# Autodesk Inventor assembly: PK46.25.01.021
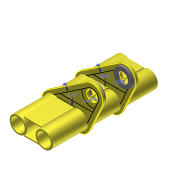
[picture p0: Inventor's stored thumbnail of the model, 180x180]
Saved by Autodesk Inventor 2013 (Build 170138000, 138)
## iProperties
Created: 2005-04
Part Number: PK46.25.01.021
Document SubType Name: Assembly
Designer: salex
Manufacturer: Standard
Standards Organization: Custom
Mass: 158322 g
Surface Area: 29326.4 cm^2
Volume: 20142.8 cm^3
Density: 7.86 g/cm^3
Author: salex
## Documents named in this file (7)
- C:\Product Design Suite 2013\Chassis, Front_Layout\Workspace\Assy, Chassis, Front\PK46.25.01.021.iam
- C:\Product Design Suite 2013\Chassis, Front_Layout\Workspace\Assy, Chassis, Front\PK46.25.01.006.ipt
- C:\Product Design Suite 2013\Chassis, Front_Layout\Workspace\Assy, Chassis, Front\PK46.25.01.007.ipt
- C:\Product Design Suite 2013\Chassis, Front_Layout\Workspace\Assy, Chassis, Front\PK46.25.01.009.ipt
- C:\Product Design Suite 2013\Chassis, Front_Layout\Workspace\Assy, Chassis, Front\PK46.25.01.009-01.ipt
- C:\Product Design Suite 2013\Chassis, Front_Layout\Workspace\Assy, Chassis, Front\PK46.25.01.016.ipt
- C:\Product Design Suite 2013\Chassis, Front_Layout\Workspace\Assy, Chassis, Front\PK46.25.01.105.ipt
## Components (12 placed, 6 different names)
1. PK46.25.01.105:1 — Mate:1, Mate:2, Insert:2, Flush:2, Mate:7, Mate:9, Mate:11, Mate:12, Mate:13
2. PK46.25.01.105:2 — Mate:3, Mate:4, Insert:1, Mate:6, Mate:8
3. PK46.25.01.006:1 — Insert:2, Mate:5
4. PK46.25.01.006:2 — Insert:1, Mate:5
5. PK46.25.01.007:1 — Mate:2, Flush:1, Mate:4, Tangent:2
6. PK46.25.01.007:2 — Mate:1, Flush:1, Mate:3, Flush:2, Mate:10, Tangent:1, Tangent:3
7. PK46.25.01.009:1 — Mate:11, Flush:8, Flush:9
8. PK46.25.01.009-01:1 — Mate:7, Flush:3, Mate:10, Tangent:1, Tangent:2, Flush:4, Flush:5, Angle:1, Flush:10
9. PK46.25.01.009-01:2 — Mate:8, Flush:6, Flush:7, Flush:8, Flush:9
10. PK46.25.01.009-01:3 — Mate:9, Flush:3, Tangent:3, Flush:6
11. PK46.25.01.009-01:4 — Mate:6, Flush:4, Flush:5, Flush:7
12. PK46.25.01.016:1 — Mate:12, Angle:1, Mate:13, Flush:10
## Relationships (29: Mate 13, Flush 10, Tangent 3, Insert 2, Angle 1)
- Mate:1: PK46.25.01.105:1 ↔ PK46.25.01.007:2
- Mate:2: PK46.25.01.105:1 ↔ PK46.25.01.007:1
- Flush:1: PK46.25.01.007:1 ↔ PK46.25.01.007:2
- Mate:3: PK46.25.01.105:2 ↔ PK46.25.01.007:2
- Mate:4: PK46.25.01.105:2 ↔ PK46.25.01.007:1
- Insert:1: PK46.25.01.105:2 ↔ PK46.25.01.006:2
- Insert:2: PK46.25.01.105:1 ↔ PK46.25.01.006:1
- Mate:5: PK46.25.01.006:1 ↔ PK46.25.01.006:2
- Flush:2: PK46.25.01.105:1 ↔ PK46.25.01.007:2
- Mate:6: PK46.25.01.105:2 ↔ PK46.25.01.009-01:4
- Mate:7: PK46.25.01.105:1 ↔ PK46.25.01.009-01:1
- Mate:8: PK46.25.01.105:2 ↔ PK46.25.01.009-01:2
- Mate:9: PK46.25.01.105:1 ↔ PK46.25.01.009-01:3
- Flush:3: PK46.25.01.009-01:1 ↔ PK46.25.01.009-01:3
- Mate:10: PK46.25.01.007:2 ↔ PK46.25.01.009-01:1
- Tangent:1: PK46.25.01.007:2 ↔ PK46.25.01.009-01:1
- Tangent:2: PK46.25.01.007:1 ↔ PK46.25.01.009-01:1
- Tangent:3: PK46.25.01.007:2 ↔ PK46.25.01.009-01:3
- Flush:4: PK46.25.01.009-01:1 ↔ PK46.25.01.009-01:4
- Flush:5: PK46.25.01.009-01:1 ↔ PK46.25.01.009-01:4
- Flush:6: PK46.25.01.009-01:2 ↔ PK46.25.01.009-01:3
- Flush:7: PK46.25.01.009-01:2 ↔ PK46.25.01.009-01:4
- Mate:11: PK46.25.01.105:1 ↔ PK46.25.01.009:1
- Flush:8: PK46.25.01.009:1 ↔ PK46.25.01.009-01:2
- Flush:9: PK46.25.01.009:1 ↔ PK46.25.01.009-01:2
- Mate:12: PK46.25.01.105:1 ↔ PK46.25.01.016:1
- Angle:1: PK46.25.01.009-01:1 ↔ PK46.25.01.016:1
- Mate:13: PK46.25.01.105:1 ↔ PK46.25.01.016:1
- Flush:10: PK46.25.01.009-01:1 ↔ PK46.25.01.016:1
## Named parameters: sa_0 = 6500000 mm
